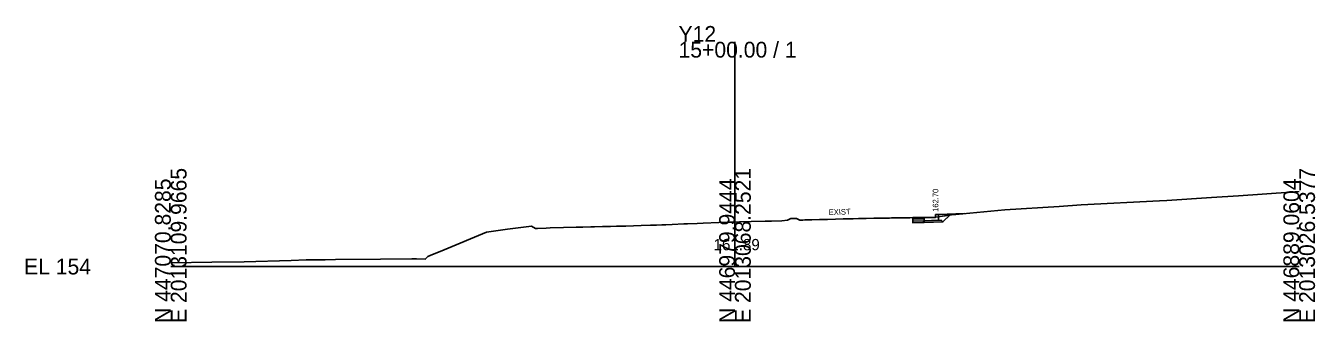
# Model space of a CAD drawing. Extents: x -26 to 1203, y -10 to 9542.
# Drawn here: x 974.3 to 1202.8, y -9.7 to 42.7 of the extents above; entities that cross this region are included whole.
import ezdxf

# ---------------------------------------------------------------- set-up
doc = ezdxf.new("R2010")
doc.units = 0
for name, color, linetype in [('Default', 7, 'Continuous'), ('Exist Cross Section Cell', 7, 'Continuous'), ('Exist XS Center Line Elevation Label', 7, 'Continuous'), ('Exist XS Ground Line', 7, 'Continuous'), ('Prop CMT Conc Surface', 7, 'Continuous'), ('Prop CMT Concrete Structures', 7, 'Continuous'), ('Prop CMT Pvmt Course 1', 7, 'Continuous'), ('Prop CMT Pvmt Course 1 CG', 7, 'Continuous'), ('Prop CMT Pvmt Course 2', 7, 'Continuous'), ('Prop CMT Pvmt Course 3', 7, 'Continuous'), ('Prop CMT Pvmt Surface', 7, 'Continuous'), ('Prop CMT Slope Grass', 7, 'Continuous'), ('Prop CMT Subgrade Earthwork', 7, 'Continuous'), ('Prop XS Earthwork Shape', 7, 'Continuous'), ('Prop XS Hydro Elevations', 7, 'Continuous'), ('Prop XS SE Text', 7, 'Continuous')]:
    doc.layers.add(name, color=color, linetype=linetype)

msp = doc.modelspace()

# ---------------------------------------------------------------- linework, layer by layer
at = {"layer": 'Exist Cross Section Cell'}
for p, q in [((1100, 0), (1100, 39.84)), ((1000, 0), (1100, 0)), ((1100, 0), (1200, 0))]:
    msp.add_line(p, q, dxfattribs=at)
at = {"layer": 'Exist XS Ground Line'}
msp.add_lwpolyline([(1000, 0.66), (1007.31, 0.75), (1013.02, 0.85), (1021.36, 1.08), (1024.02, 1.18), (1025.96, 1.19), (1026.48, 1.19), (1027.34, 1.2), (1029.22, 1.22), (1037.2, 1.31), (1042.73, 1.36), (1043.23, 1.38), (1043.54, 1.39), (1045.12, 1.29), (1045.54, 1.79), (1045.97, 1.95), (1048.48, 2.99), (1055.95, 6.12), (1059.71, 6.62), (1063.96, 7.18), (1064.67, 6.73), (1065.03, 6.75), (1066.53, 6.81), (1067.22, 6.84), (1069.61, 6.91), (1071.84, 6.97), (1072.57, 6.99), (1073.01, 7), (1074.46, 7.04), (1075.13, 7.05), (1076.53, 7.07), (1077.29, 7.08), (1077.95, 7.1), (1078.98, 7.13), (1080.64, 7.18), (1082.02, 7.22), (1083.38, 7.27), (1085.01, 7.32), (1086.12, 7.36), (1087.03, 7.39), (1087.74, 7.42), (1088.85, 7.47), (1090.93, 7.55), (1091.6, 7.57), (1093.28, 7.65), (1094.35, 7.71), (1097.14, 7.82), (1098.64, 7.86), (1099.02, 7.87), (1100, 7.89), (1100.82, 7.91), (1102.9, 7.96), (1105.33, 8.02), (1106.46, 8.05), (1108.28, 8.11), (1109.33, 8.24), (1109.93, 8.54), (1110.92, 8.54), (1111.52, 8.24), (1112.02, 8.25), (1112.38, 8.26), (1113.65, 8.29), (1114.98, 8.33), (1116.39, 8.36), (1117.83, 8.4), (1119.15, 8.43), (1120.95, 8.48), (1121.9, 8.51), (1122.6, 8.52), (1123.25, 8.53), (1124.61, 8.55), (1126.9, 8.59), (1127.37, 8.6), (1127.77, 8.61), (1130.09, 8.64), (1130.98, 8.66), (1132.87, 8.7), (1133.55, 8.71), (1135.04, 8.72), (1135.52, 8.74), (1138.31, 9.15), (1138.72, 9.22), (1139.13, 9.25), (1147.81, 10.07), (1157.43, 10.65), (1161.36, 10.93), (1175.22, 11.63), (1176.57, 11.71), (1184.47, 12.26), (1189.23, 12.53), (1198.45, 13.21), (1200, 13.28)], dxfattribs=at)
at = {"layer": 'Prop CMT Conc Surface'}
msp.add_lwpolyline([(1133.55, 8.71), (1135.55, 8.7), (1135.55, 9.2), (1136.05, 9.2)], dxfattribs=at)
at = {"layer": 'Prop CMT Concrete Structures'}
for points in [[(1133.55, 8.71), (1135.55, 8.7), (1135.55, 9.2), (1136.05, 9.2)], [(1136.05, 9.2), (1136.05, 8.21), (1133.55, 8.13)], [(1133.55, 8.13), (1133.55, 8.71)]]:
    msp.add_lwpolyline(points, dxfattribs=at)
at = {"layer": 'Prop CMT Pvmt Course 1'}
for points in [[(1131.54, 8.65), (1133.55, 8.71)], [(1131.54, 8.65), (1131.54, 8.65)], [(1131.54, 8.4), (1131.54, 8.65)], [(1133.55, 8.46), (1131.54, 8.4)], [(1133.55, 8.71), (1133.55, 8.46)]]:
    msp.add_lwpolyline(points, dxfattribs=at)
at = {"layer": 'Prop CMT Pvmt Course 1 CG'}
for points in [[(1133.55, 8.13), (1136.55, 8.22), (1136.87, 7.9)], [(1133.55, 7.79), (1133.55, 8.13)], [(1136.87, 7.9), (1133.55, 7.79)]]:
    msp.add_lwpolyline(points, dxfattribs=at)
at = {"layer": 'Prop CMT Pvmt Course 2'}
for points in [[(1131.54, 8.4), (1133.55, 8.46)], [(1131.54, 8.06), (1131.54, 8.4)], [(1133.55, 8.13), (1131.54, 8.06)], [(1133.55, 8.46), (1133.55, 8.13)]]:
    msp.add_lwpolyline(points, dxfattribs=at)
at = {"layer": 'Prop CMT Pvmt Course 3'}
for points in [[(1131.54, 8.06), (1133.55, 8.13)], [(1131.54, 7.73), (1131.54, 8.06)], [(1133.55, 7.79), (1131.54, 7.73)], [(1133.55, 8.13), (1133.55, 7.79)]]:
    msp.add_lwpolyline(points, dxfattribs=at)
at = {"layer": 'Prop CMT Pvmt Surface'}
msp.add_lwpolyline([(1131.54, 8.65), (1133.55, 8.71)], dxfattribs=at)
at = {"layer": 'Prop CMT Slope Grass'}
msp.add_lwpolyline([(1136.05, 9.2), (1140.67, 9.4)], dxfattribs=at)
at = {"layer": 'Prop CMT Subgrade Earthwork'}
for points in [[(1133.55, 7.79), (1136.87, 7.9), (1138.27, 9.29)], [(1131.54, 7.73), (1131.54, 8.67)], [(1131.54, 7.73), (1133.55, 7.79)], [(1133.55, 7.79), (1131.54, 7.73)]]:
    msp.add_lwpolyline(points, dxfattribs=at)
at = {"layer": 'Prop XS Earthwork Shape'}
for points in [[(1138.09, 9.12), (1138.27, 9.29), (1140.67, 9.4), (1138.72, 9.22)], [(1131.54, 8.67), (1131.54, 7.73), (1136.87, 7.9), (1138.09, 9.12), (1135.52, 8.74), (1133.55, 8.71)]]:
    msp.add_lwpolyline(points, close=True, dxfattribs=at)

# ---------------------------------------------------------------- texts
at = {"layer": 'Default'}
msp.add_text('-', height=0.0001, dxfattribs=at).set_placement((1000, 0))
at = {"layer": 'Exist Cross Section Cell'}
for s, p in [('Y12', (1090, 39.84)), ('15+00.00 / 1', (1090, 37.04)), ('EL 154', (974, -1.4))]:
    msp.add_text(s, height=2.8, dxfattribs=at).set_placement(p)
for s, p in [('E 2013109.9665', (1002.8, -10)), ('E 2013068.2521', (1102.8, -10)), ('E 2013026.5377', (1202.8, -10)), ('N 447070.8285', (1000, -10)), ('N 446979.9444', (1100, -10)), ('N 446889.0604', (1200, -10))]:
    msp.add_text(s, height=2.8, rotation=90, dxfattribs=at).set_placement(p)
at = {"layer": 'Exist XS Center Line Elevation Label'}
msp.add_text('161.89', height=2, dxfattribs=at).set_placement((1096.21, 2.89))
at = {"layer": 'Prop XS Hydro Elevations'}
msp.add_text('162.70', height=1, rotation=90, dxfattribs=at).set_placement((1136.05, 9.7))
at = {"layer": 'Prop XS SE Text'}
msp.add_text('EXIST', height=1, rotation=1.8605, dxfattribs=at).set_placement((1116.63, 9.12))

doc.saveas('drawing.dxf')
